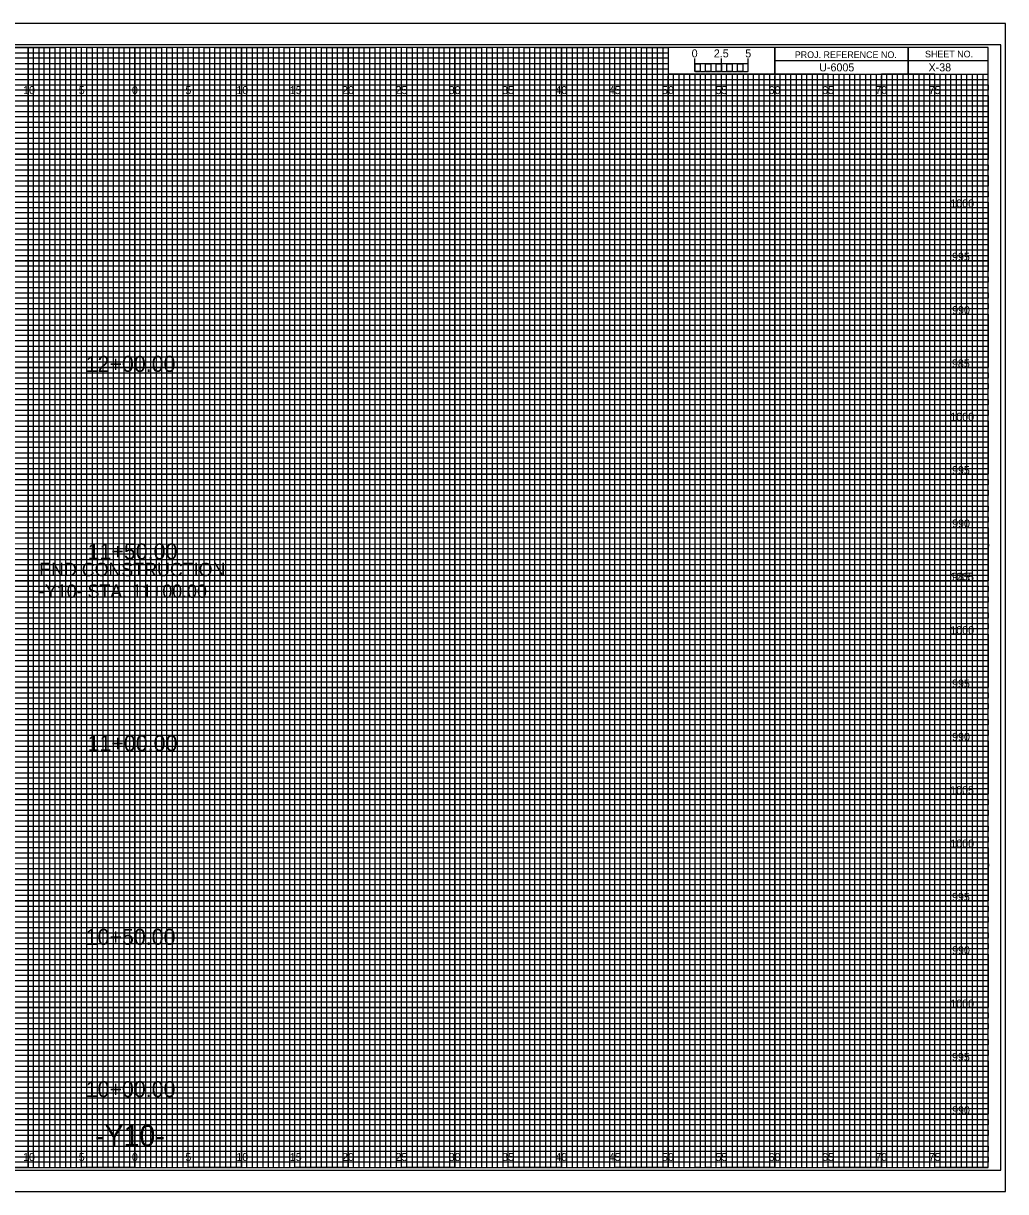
# Model space of a CAD drawing. Extents: x -7 to 162, y -2 to 107.
# Drawn here: x 69.5 to 161.7, y -2.3 to 107.3 of the extents above; entities that cross this region are included whole.
import ezdxf

# ---------------------------------------------------------------- set-up
doc = ezdxf.new("R2010")
doc.units = 0
for name, color, linetype in [('Prop XS Alignment Label', 7, 'Continuous'), ('Prop XS Bar Scale Labels', 7, 'Continuous'), ('Prop XS Elevation Labels', 7, 'Continuous'), ('Prop XS Label Text', 7, 'Continuous'), ('Prop XS Offset Labels', 7, 'Continuous'), ('Prop XS Project Number', 7, 'Continuous'), ('Prop XS Sheet Number', 7, 'Continuous'), ('Prop XS Station Labels', 7, 'Continuous'), ('Sheet Cross Section CELL', 7, 'Continuous'), ('Sheet Cross Section Grid Major CELL', 7, 'Continuous'), ('Sheet Cross Section Grid Middle CELL', 7, 'Continuous'), ('Sheet Cross Section Grid Minor 1 CELL', 7, 'Continuous'), ('Sheet Cross Section Grid Minor 2 CELL', 7, 'Continuous'), ('Sheet Cross Section Scale CELL', 7, 'Continuous'), ('Sheet Cutting Line CELL', 7, 'Continuous'), ('Sheet DOT Grid CELL', 7, 'Continuous'), ('Sheet Plot Border Inside CELL', 7, 'Continuous'), ('Sheet Plot Border Outside CELL', 7, 'Continuous')]:
    doc.layers.add(name, color=color, linetype=linetype)

msp = doc.modelspace()

# ---------------------------------------------------------------- linework, layer by layer
at = {"layer": 'Sheet Cross Section CELL'}
for p, q in [((152.5, 105), (152.5, 102.5)), ((152.5, 102.5), (152.5, 105)), ((160, 103.75), (140, 103.75)), ((140, 103.75), (140, 102.5)), ((140, 102.5), (160, 102.5))]:
    msp.add_line(p, q, dxfattribs=at)
for points in [[(160, 105), (0, 105), (0, 0), (160, 0)], [(140, 105), (130, 105), (130, 102.52), (140, 102.52)], [(160, 105), (140, 105), (140, 102.5), (160, 102.5)]]:
    msp.add_lwpolyline(points, close=True, dxfattribs=at)
at = {"layer": 'Sheet Cross Section Grid Major CELL'}
for p, q in [((75, 105), (70, 105)), ((70, 105), (70, 0)), ((75, 0), (75, 105)), ((85, 105), (80, 105)), ((80, 105), (80, 0)), ((85, 0), (85, 105)), ((95, 105), (90, 105)), ((90, 105), (90, 0)), ((95, 0), (95, 105)), ((105, 105), (100, 105)), ((100, 105), (100, 0)), ((105, 0), (105, 105)), ((115, 105), (110, 105)), ((110, 105), (110, 0)), ((115, 0), (115, 105)), ((125, 105), (120, 105)), ((120, 105), (120, 0)), ((125, 0), (125, 105)), ((130, 105), (130, 0)), ((135, 0), (135, 102.5)), ((145, 102.5), (140, 102.5)), ((140, 102.5), (140, 0)), ((145, 0), (145, 102.5)), ((155, 102.5), (150, 102.5)), ((150, 102.5), (150, 0)), ((155, 0), (155, 102.5)), ((70, 0), (65, 0)), ((80, 0), (75, 0)), ((90, 0), (85, 0)), ((100, 0), (95, 0)), ((110, 0), (105, 0)), ((120, 0), (115, 0)), ((130, 0), (125, 0)), ((140, 0), (135, 0)), ((150, 0), (145, 0)), ((160, 0), (155, 0)), ((160, 0), (160, 0))]:
    msp.add_line(p, q, dxfattribs=at)
for points in [[(0, 100), (160, 100), (160, 95), (0, 95)], [(0, 90), (160, 90), (160, 85), (0, 85)], [(0, 80), (160, 80), (160, 75), (0, 75)], [(0, 70), (160, 70), (160, 65), (0, 65)], [(0, 60), (160, 60), (160, 55), (0, 55)], [(0, 50), (160, 50), (160, 45), (0, 45)], [(0, 40), (160, 40), (160, 35), (0, 35)], [(0, 30), (160, 30), (160, 25), (0, 25)], [(0, 20), (160, 20), (160, 15), (0, 15)], [(0, 10), (160, 10), (160, 5), (0, 5)]]:
    msp.add_lwpolyline(points, dxfattribs=at)
at = {"layer": 'Sheet Cross Section Grid Middle CELL'}
for points in [[(67.5, 105), (72.5, 105), (72.5, 0), (77.5, 0), (77.5, 105), (82.5, 105), (82.5, 0), (87.5, 0), (87.5, 105), (92.5, 105), (92.5, 0), (97.5, 0), (97.5, 105), (102.5, 105), (102.5, 0), (107.5, 0), (107.5, 105), (112.5, 105), (112.5, 0), (117.5, 0), (117.5, 105), (122.5, 105), (122.5, 0), (127.5, 0), (127.5, 105), (129.97, 105), (130, 105), (130, 102.5), (132.5, 102.5), (132.5, 0), (137.5, 0), (137.5, 102.5), (142.5, 102.5), (142.5, 0), (147.5, 0), (147.5, 102.5), (152.5, 102.5), (152.5, 0), (157.5, 0), (157.5, 102.5)], [(0, 102.5), (137.5, 102.5)], [(0, 92.5), (160, 92.5), (160, 97.5), (0, 97.5)], [(0, 82.5), (160, 82.5), (160, 87.5), (0, 87.5)], [(0, 72.5), (160, 72.5), (160, 77.5), (0, 77.5)], [(0, 62.5), (160, 62.5), (160, 67.5), (0, 67.5)], [(0, 52.5), (160, 52.5), (160, 57.5), (0, 57.5)], [(0, 42.5), (160, 42.5), (160, 47.5), (0, 47.5)], [(0, 32.5), (160, 32.5), (160, 37.5), (0, 37.5)], [(0, 22.5), (160, 22.5), (160, 27.5), (0, 27.5)], [(0, 12.5), (160, 12.5), (160, 17.5), (0, 17.5)], [(0, 2.5), (160, 2.5), (160, 7.5), (0, 7.5)]]:
    msp.add_lwpolyline(points, dxfattribs=at)
at = {"layer": 'Sheet Cross Section Grid Minor 1 CELL'}
for p, q in [((0, 104.5), (130, 104.5)), ((130, 104.5), (130, 103.99)), ((130, 103.99), (0, 103.99)), ((0, 103.5), (130, 103.5)), ((130, 102.95), (0, 102.95)), ((130, 103.5), (130, 102.95)), ((0, 102), (160, 102))]:
    msp.add_line(p, q, dxfattribs=at)
for points in [[(0, 101.5), (135, 101.5), (160, 101.5), (160, 101), (0, 101)], [(0, 100.5), (160, 100.5), (160, 99.5), (0, 99.5)], [(0, 99), (160, 99), (160, 98.5), (0, 98.49)], [(0, 98), (160, 98), (160, 97), (0, 97)], [(0, 96.5), (160, 96.5), (160, 96), (0, 96)], [(0, 95.5), (160, 95.5), (160, 94.5), (0, 94.5)], [(0, 94), (160, 94), (160, 93.5), (0, 93.5)], [(0, 93), (160, 93), (160, 92), (0, 92)], [(0, 91.5), (160, 91.5), (160, 91), (0, 91)], [(0, 90.5), (160, 90.5), (160, 89.5), (0, 89.5)], [(0, 89), (160, 89), (160, 88.5), (0, 88.5)], [(0, 88), (160, 88), (160, 86.98), (160, 86.5), (160, 86), (0, 86)], [(0, 87), (160, 87), (160, 86.5), (0, 86.5)], [(0, 85.5), (160, 85.5), (160, 84.5), (0, 84.52)], [(0, 84.52), (160, 84.5), (160, 84), (0, 84)], [(0, 83.5), (160, 83.5), (160, 83), (0, 83)], [(0, 82), (160, 82), (160, 81.5), (0, 81.5)], [(0, 81), (160, 81), (160, 80.5), (0, 80.5)], [(-0.04, 79.45), (160, 79.45), (160, 78.94), (-0.04, 78.94)], [(0, 78.5), (160, 78.5), (160, 78), (0, 78)], [(0, 77), (160, 77), (160, 76.5), (0, 76.5)], [(0, 76), (160, 76), (160, 75.5), (0, 75.5)], [(0, 74.5), (160, 74.5), (160, 74), (0, 74)], [(0, 73.5), (160, 73.5), (160, 73), (0, 73)], [(0, 72), (160, 72), (160, 71.5), (0, 71.5)], [(0, 71), (160, 71), (160, 70.5), (0, 70.5)], [(0, 69.5), (160, 69.5), (160, 68.99), (0, 69)], [(0, 68.5), (160, 68.5), (160, 68), (0, 68)], [(0, 67), (160, 67), (160, 66.5), (0, 66.5)], [(0, 66), (160, 66), (160, 65.5), (0, 65.5)], [(0, 64.5), (160, 64.5), (160, 64), (0, 64)], [(0, 63.5), (160, 63.5), (160, 63), (0, 63)], [(0, 62), (160, 62), (160, 61.5), (0, 61.5)], [(0, 61), (160, 61), (160, 60.5), (0, 60.5)], [(0, 59.5), (160, 59.5), (160, 59), (0, 59)], [(0, 58.5), (160.03, 58.45), (160, 58), (0, 58)], [(0, 57), (160, 57), (160, 56.5), (0, 56.5)], [(0, 56), (160, 56), (160, 55.5), (0, 55.5)], [(0, 54.5), (160, 54.5), (160, 54), (0, 54)], [(0, 53.5), (160, 53.5), (160, 53), (0, 53)], [(0, 52), (160, 52), (160, 51.5), (0, 51.5)], [(0, 51), (160, 51), (160, 50.5), (0, 50.5)], [(0, 49.5), (160, 49.5), (160, 49), (0, 49)], [(0, 48.5), (160, 48.5), (160, 48), (0, 48)], [(0, 47), (160, 47), (160, 46.5), (0, 46.5)], [(0, 46), (160, 46), (160, 45.5), (0, 45.5)], [(0, 44.5), (160, 44.5), (160, 44), (0, 44)], [(0, 43.5), (160, 43.5), (160, 43), (0, 43)], [(0, 42), (160, 42), (160, 41.5), (0, 41.5)], [(0, 41), (160, 41), (160, 40.5), (0, 40.5)], [(0, 39.5), (160, 39.5), (160, 38.99), (0, 39)], [(0, 38.5), (160, 38.5), (160, 38), (0, 38)], [(0, 37), (160, 37), (160, 36.5), (0, 36.5)], [(0, 36), (160, 36), (160, 35.5), (0, 35.5)], [(0, 34.5), (160, 34.5), (160, 34), (0, 34)], [(0, 33.5), (160, 33.5), (160, 33), (0, 33)], [(0, 32), (160, 32), (160, 31.5), (0, 31.5)], [(0, 31), (160, 31), (160, 30.5), (0, 30.5)], [(0, 29.5), (160, 29.5), (160, 29), (0, 29)], [(0, 28.5), (160.03, 28.46), (160, 28), (0, 28)], [(0, 27), (160, 27), (160, 26.5), (0, 26.5)], [(0, 26), (160, 26), (160, 25.5), (0, 25.5)], [(0, 24.5), (160, 24.5), (160, 24), (0, 24)], [(0, 23.5), (160, 23.5), (160, 23), (0, 23)], [(0, 22), (160, 22), (160, 21.5), (0, 21.5)], [(0, 21), (160, 21), (160, 20.5), (0, 20.5)], [(0, 19.5), (160, 19.5), (160, 19), (0, 19)], [(0, 18.5), (160, 18.5), (160, 18), (0, 18)], [(0, 17), (160, 17), (160, 16.5), (0, 16.5)], [(0, 16), (160, 16), (160, 15.5), (0, 15.5)], [(0, 14.5), (160, 14.5), (160, 14), (0, 14)], [(0, 13.5), (160, 13.5), (160, 13), (0, 13)], [(0, 12), (160, 12), (160, 11.5), (0, 11.5)], [(0, 11), (160, 11), (160, 10.5), (0, 10.5)], [(0, 9.5), (160, 9.5), (160, 9), (0, 9)], [(0, 8.5), (160, 8.5), (160, 8), (0, 8)], [(0, 7), (160, 7), (160, 6.5), (0, 6.5)], [(0, 6), (160, 6), (160, 5.5), (0, 5.5)], [(0, 4.5), (160, 4.5), (160, 4), (0, 4)], [(0, 3.5), (160, 3.5), (160, 3), (0, 3)], [(0, 2), (160, 2), (160, 1.5), (0, 1.5)], [(0, 1), (160, 1), (160, 0.5), (0, 0.5)]]:
    msp.add_lwpolyline(points, dxfattribs=at)
at = {"layer": 'Sheet Cross Section Grid Minor 2 CELL'}
for p, q in [((133.5, 102.5), (133, 102.5)), ((133, 102.5), (133, 0)), ((133.5, 0), (133.5, 102.5)), ((134.5, 102.5), (134, 102.5)), ((134, 102.5), (134, 0)), ((134.5, 0), (134.5, 102.5)), ((133, 0), (132.5, 0)), ((134, 0), (133.5, 0))]:
    msp.add_line(p, q, dxfattribs=at)
for points in [[(70, 0), (70.5, 0), (70.5, 105), (71, 105), (71, 0)], [(71, 0), (71.5, 0), (71.5, 105), (72, 105), (72, 0)], [(72.5, 0), (73, 0), (73, 105), (73.5, 105), (73.5, 0)], [(73.5, 0), (74, 0), (74, 105), (74.5, 105), (74.5, 0)], [(75, 0), (75.5, 0), (75.5, 105), (76, 105), (76, 0)], [(76, 0), (76.5, 0), (76.5, 105), (77, 105), (77, 0)], [(77.5, 0), (78, 0), (78, 105), (78.5, 105), (78.5, 0)], [(78.5, 0), (79, 0), (79, 105), (79.5, 105), (79.5, 0)], [(80, 0), (80.5, 0), (80.5, 105), (81, 105), (81, 0)], [(81, 0), (81.5, 0), (81.5, 105), (82, 105), (82, 0)], [(82.5, 0), (83, 0), (83, 105), (83.5, 105), (83.5, 0)], [(83.5, 0), (84, 0), (84, 105), (84.5, 105), (84.5, 0)], [(85, 0), (85.5, 0), (85.5, 105), (86, 105), (86, 0)], [(86, 0), (86.5, 0), (86.5, 105), (87, 105), (87, 0)], [(87.5, 0), (88, 0), (88, 105), (88.5, 105), (88.5, 0)], [(88.5, 0), (89, 0), (89, 105), (89.5, 105), (89.5, 0)], [(90, 0), (90.5, 0), (90.5, 105), (91, 105), (91, 0)], [(91, 0), (91.5, 0), (91.5, 105), (92, 105), (92, 0)], [(92.5, 0), (93, 0), (93, 105), (93.5, 105), (93.5, 0)], [(93.5, 0), (94, 0), (94, 105), (94.5, 105), (94.5, 0)], [(95, 0), (95.5, 0), (95.5, 105), (96, 105), (96, 0)], [(96, 0), (96.5, 0), (96.5, 105), (97, 105), (97, 0)], [(97.5, 0), (98, 0), (98, 105), (98.5, 105), (98.5, 0)], [(98.5, 0), (99, 0), (99, 105), (99.5, 105), (99.5, 0)], [(100, 0), (100.5, 0), (100.5, 105), (101, 105), (101, 0)], [(101, 0), (101.5, 0), (101.5, 105), (102, 105), (102, 0)], [(102.5, 0), (103, 0), (103, 105), (103.5, 105), (103.5, 0)], [(103.5, 0), (104, 0), (104, 105), (104.5, 105), (104.5, 0)], [(105, 0), (105.5, 0), (105.5, 105), (106, 105), (106, 0)], [(106, 0), (106.5, 0), (106.5, 105), (107, 105), (107, 0)], [(107.5, 0), (108, 0), (108, 105), (108.5, 105), (108.5, 0)], [(108.5, 0), (109, 0), (109, 105), (109.5, 105), (109.5, 0)], [(110, 0), (110.5, 0), (110.5, 105), (111, 105), (111, 0)], [(111, 0), (111.5, 0), (111.5, 105), (112, 105), (112, 0)], [(112.5, 0), (113, 0), (113, 105), (113.5, 105), (113.5, 0)], [(113.5, 0), (114, 0), (114, 105), (114.5, 105), (114.5, 0)], [(115, 0), (115.5, 0), (115.5, 105), (116, 105), (116, 0)], [(116, 0), (116.5, 0), (116.5, 105), (117, 105), (117, 0)], [(117.5, 0), (118, 0), (118, 105), (118.5, 105), (118.5, 0)], [(118.5, 0), (119, 0), (119, 105), (119.5, 105), (119.5, 0)], [(120, 0), (120.5, 0), (120.5, 105), (121, 105), (121, 0)], [(121, 0), (121.5, 0), (121.5, 105), (122, 105), (122, 0)], [(122.5, 0), (123, 0), (123, 105), (123.5, 105), (123.5, 0)], [(123.5, 0), (124, 0), (124, 105), (124.5, 105), (124.5, 0)], [(125, 0), (125.5, 0), (125.5, 105), (126, 105), (126, 0)], [(126, 0), (126.5, 0), (126.5, 105), (127, 105), (127, 0)], [(127.5, 0), (128, 0), (128, 105), (128.5, 105), (128.5, 0)], [(128.5, 0), (129, 0), (129, 105), (129.5, 105), (129.5, 0)], [(130, 0), (130.5, 0), (130.5, 102.5), (131.01, 102.5), (131.01, 0)], [(131, 0), (131.5, 0), (131.5, 102.5), (132, 102.5), (132, 0)], [(135, 0), (135.49, 0), (135.49, 102.5), (136, 102.5), (136, 0)], [(136, 0), (136.5, 0), (136.5, 102.5), (137.03, 102.5), (137.03, 0)], [(137.5, 0), (138, 0), (138, 102.5), (138.5, 102.5), (138.5, 0)], [(138.5, 0), (139, 0), (139, 102.5), (139.5, 102.5), (139.5, 0)], [(140, 0), (140.5, 0), (140.5, 102.5), (141, 102.5), (141, 0)], [(141, 0), (141.5, 0), (141.5, 102.5), (142, 102.5), (142, 0)], [(142.5, 0), (143, 0), (143, 102.5), (143.5, 102.5), (143.5, 0)], [(143.5, 0), (144, 0), (144, 102.5), (144.5, 102.5), (144.5, 0)], [(145, 0), (145.5, 0), (145.5, 102.5), (146, 102.5), (146, 0)], [(146, 0), (146.5, 0), (146.5, 102.5), (147, 102.5), (147, 0)], [(147.5, 0), (148, 0), (148, 102.5), (148.5, 102.5), (148.5, 0)], [(148.5, 0), (149, 0), (149, 102.5), (149.5, 102.5), (149.5, 0)], [(150, 0), (150.5, 0), (150.5, 102.5), (151, 102.5), (151, 0)], [(151, 0), (151.5, 0), (151.5, 102.5), (152, 102.5), (152, 0)], [(152.5, 0), (153, 0), (153, 102.5), (153.5, 102.5), (153.5, 0)], [(153.5, 0), (154, 0), (154, 102.5), (154.5, 102.5), (154.5, 0)], [(155, 0), (155.5, 0), (155.5, 102.5), (156, 102.5), (156, 0)], [(156, 0), (156.5, 0), (156.5, 102.5), (157, 102.5), (157, 0)], [(157.5, 0), (158, 0), (158, 102.5), (158.5, 102.5), (158.5, 0)], [(158.5, 0), (159, 0), (159, 102.5), (159.5, 102.5), (159.5, 0)]]:
    msp.add_lwpolyline(points, dxfattribs=at)
at = {"layer": 'Sheet Cross Section Scale CELL'}
for p, q in [((132.5, 102.75), (132.5, 103.95)), ((132.5, 103.45), (132.5, 103.95)), ((135, 102.75), (135, 103.95)), ((137.5, 102.75), (137.5, 103.95)), ((137.5, 103.45), (137.5, 103.95))]:
    msp.add_line(p, q, dxfattribs=at)
for points in [[(137.5, 103.45), (132.5, 103.45), (132.5, 102.75), (137.5, 102.75)], [(132.5, 103.45), (133, 103.45), (133, 102.75), (132.5, 102.75)], [(133.5, 103.45), (134, 103.45), (134, 102.75), (133.5, 102.75)], [(134.5, 103.45), (135, 103.45), (135, 102.75), (134.5, 102.75)], [(135.5, 103.45), (136, 103.45), (136, 102.75), (135.5, 102.75)], [(136.5, 103.45), (137, 103.45), (137, 102.75), (136.5, 102.75)]]:
    msp.add_lwpolyline(points, close=True, dxfattribs=at)
at = {"layer": 'Sheet Cutting Line CELL'}
for p, q in [((161.65, 107.25), (-6.7, 107.25)), ((-6.7, -2.25), (161.65, -2.25))]:
    msp.add_line(p, q, dxfattribs=at)
at = {"layer": 'Sheet DOT Grid CELL'}
for p, q in [((70, 0), (70, 105)), ((75, 0), (75, 105)), ((80, 0), (80, 105)), ((85, 0), (85, 105)), ((90, 0), (90, 105)), ((95, 0), (95, 105)), ((100, 0), (100, 105)), ((105, 0), (105, 105)), ((110, 0), (110, 105)), ((115, 0), (115, 105)), ((120, 0), (120, 105)), ((125, 0), (125, 105)), ((130, 0), (130, 102.34)), ((135, 0), (135, 102.34)), ((140, 0), (140, 102.34)), ((145, 0), (145, 102.34)), ((150, 0), (150, 102.34)), ((155, 0), (155, 102.34)), ((0, 100), (160, 100)), ((0, 95), (160, 95)), ((0, 90), (160, 90)), ((0, 85), (160, 85)), ((0, 80), (160, 80)), ((0, 75), (160, 75)), ((0, 70), (160, 70)), ((0, 65), (160, 65)), ((0, 60), (160, 60)), ((0, 55), (160, 55)), ((0, 50), (160, 50)), ((0, 45), (160, 45)), ((0, 40), (160, 40)), ((0, 35), (160, 35)), ((0, 30), (160, 30)), ((0, 25), (160, 25)), ((0, 20), (160, 20)), ((0, 15), (160, 15)), ((0, 10), (160, 10)), ((0, 5), (160, 5))]:
    msp.add_line(p, q, dxfattribs=at)
at = {"layer": 'Sheet Plot Border Inside CELL'}
msp.add_lwpolyline([(-5.4, -0.25), (161.2, -0.25), (161.2, 105.25), (-5.4, 105.25)], close=True, dxfattribs=at)
at = {"layer": 'Sheet Plot Border Outside CELL'}
msp.add_lwpolyline([(-6.7, -2.25), (161.65, -2.25), (161.65, 107.25), (-6.7, 107.25)], close=True, dxfattribs=at)

# ---------------------------------------------------------------- texts
at = {"layer": 'Prop XS Alignment Label'}
msp.add_text('-Y10-', height=2, dxfattribs=at).set_placement((76.27, 2))
at = {"layer": 'Prop XS Bar Scale Labels'}
for s, p in [('2.5', (134.29, 104.06)), ('5', (137.24, 104.06))]:
    msp.add_text(s, height=0.75, dxfattribs=at).set_placement(p)
at = {"layer": 'Prop XS Elevation Labels'}
for s, p in [('1000', (156.46, 90)), ('995', (156.62, 85)), ('990', (156.63, 80)), ('985', (156.61, 75)), ('1000', (156.46, 70)), ('995', (156.62, 65)), ('990', (156.63, 60)), ('1005', (156.45, 55)), ('985', (156.61, 55)), ('1000', (156.46, 50)), ('995', (156.62, 45)), ('990', (156.63, 40)), ('1005', (156.45, 35)), ('1000', (156.46, 30)), ('995', (156.62, 25)), ('990', (156.63, 20)), ('1000', (156.46, 15)), ('995', (156.62, 10)), ('990', (156.63, 5))]:
    msp.add_text(s, height=0.75, dxfattribs=at).set_placement(p)
at = {"layer": 'Prop XS Label Text'}
for s, p in [('END CONSTRUCTION', (71.03, 55.44)), ('-Y10- STA. 11+00.00', (71.01, 53.41))]:
    msp.add_text(s, height=1.25, dxfattribs=at).set_placement(p)
at = {"layer": 'Prop XS Offset Labels'}
for s, p in [('10', (69.52, 100.62)), ('5', (74.74, 100.62)), ('0', (79.73, 100.62)), ('0', (79.73, 100.62)), ('5', (84.74, 100.62)), ('10', (89.52, 100.62)), ('15', (94.53, 100.62)), ('20', (99.43, 100.62)), ('25', (104.44, 100.62)), ('30', (109.43, 100.62)), ('35', (114.44, 100.62)), ('40', (119.43, 100.62)), ('45', (124.44, 100.62)), ('50', (129.43, 100.62)), ('55', (134.44, 100.62)), ('60', (139.43, 100.62)), ('65', (144.44, 100.62)), ('70', (149.43, 100.62)), ('75', (154.44, 100.62)), ('10', (69.52, 0.62)), ('5', (74.74, 0.62)), ('0', (79.73, 0.62)), ('0', (79.73, 0.62)), ('5', (84.74, 0.62)), ('10', (89.52, 0.62)), ('15', (94.53, 0.62)), ('20', (99.43, 0.62)), ('25', (104.44, 0.62)), ('30', (109.43, 0.62)), ('35', (114.44, 0.62)), ('40', (119.43, 0.62)), ('45', (124.44, 0.62)), ('50', (129.43, 0.62)), ('55', (134.44, 0.62)), ('60', (139.43, 0.62)), ('65', (144.44, 0.62)), ('70', (149.43, 0.62)), ('75', (154.44, 0.62))]:
    msp.add_text(s, height=0.75, dxfattribs=at).set_placement(p)
at = {"layer": 'Prop XS Project Number'}
msp.add_text('U-6005', height=0.75, dxfattribs=at).set_placement((144.17, 102.75))
at = {"layer": 'Prop XS Sheet Number'}
msp.add_text('X-38', height=0.75, dxfattribs=at).set_placement((154.42, 102.75))
at = {"layer": 'Prop XS Station Labels'}
for s, p in [('12+00.00', (75.39, 74.58)), ('11+50.00', (75.57, 57.01)), ('11+00.00', (75.57, 39.03)), ('10+50.00', (75.39, 20.88)), ('10+00.00', (75.39, 6.61))]:
    msp.add_text(s, height=1.5, dxfattribs=at).set_placement(p)
at = {"layer": 'Sheet Cross Section CELL'}
for s, p in [('PROJ. REFERENCE NO.', (141.88, 104)), ('SHEET NO.', (154.09, 104.06))]:
    msp.add_text(s, height=0.625, dxfattribs=at).set_placement(p)
at = {"layer": 'Sheet Cross Section Scale CELL'}
msp.add_text('0', height=0.75, dxfattribs=at).set_placement((132.21, 104.06))

doc.saveas('drawing.dxf')
